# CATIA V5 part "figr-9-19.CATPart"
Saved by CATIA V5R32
Part number: Part3
Bounding box of the stored display mesh (mm): x -17.259 to 115.9, y -137.259 to 0, z -17.083 to 17.083
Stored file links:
  D:\PROJECTS\Project 2022\CATIA V5 6R 2022\Resources\Part Files\c09_catia_v5_6r2022_prt\c09_catia_v5_6r2022_prt\figr-9-19.CATPart
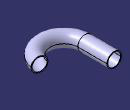
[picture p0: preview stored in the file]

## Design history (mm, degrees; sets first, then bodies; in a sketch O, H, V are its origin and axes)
Body1 (main body)
  Sketch1 on zx-plane, origin (0, 0, 0), H (-1, 0, 0), V (0, 0, 1)
    circle A1 centre (0, 0) radius 17.2586
  Sketch2 on xy-plane, origin (0, 0, 0), H (1, 0, 0), V (0, 1, 0)
    line L1 (0, 0) -> (0, -70)
    arc A1 centre (50, -70) radius 50 from (0, -70) to (50, -120) ccw
    arc A2 centre (50, -70) radius 50 from (50, -120) to (98.9898, -80) ccw
    vertical: L1 V
    tangency: A1 L1, A2 L1, A2 A1
  Rib1: profile Sketch1, centre curve Sketch2, thin wall 2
